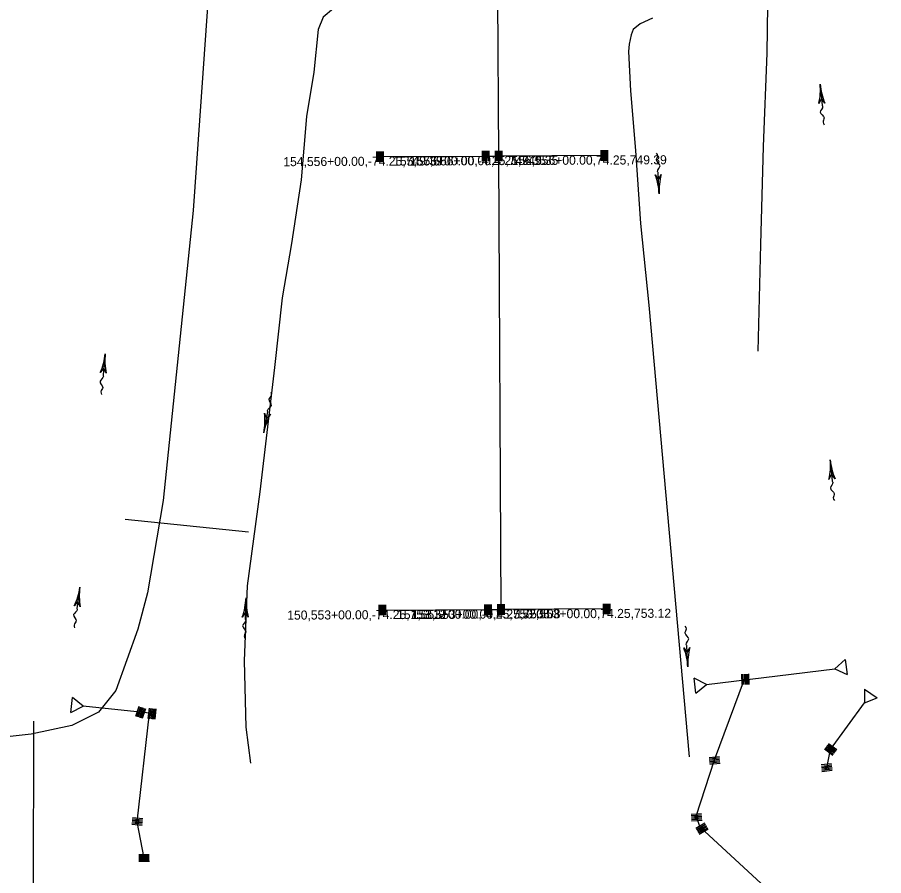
# Model space of a CAD drawing. Extents: x 593481 to 595859, y 150220 to 157407.
# Drawn here: x 594040 to 594613, y 154399 to 154967 of the extents above; entities that cross this region are included whole.
import ezdxf

# ---------------------------------------------------------------- set-up
doc = ezdxf.new("R2010")
doc.units = 0
for name, color, linetype in [('E_PROF_GridMin', 7, 'Continuous'), ('P_ALI_20_Tic', 7, 'Continuous'), ('P_ALI_50_Equation', 7, 'Continuous'), ('P_DRN_Pipes', 7, 'Continuous'), ('P_DRN_SS_UG', 7, 'Continuous'), ('P_RDWY_C_and_G_H', 7, 'Continuous')]:
    doc.layers.add(name, color=color, linetype=linetype)

msp = doc.modelspace()

# ---------------------------------------------------------------- linework, layer by layer
at = {"layer": 'E_PROF_GridMin'}
for p, q in [((594358.22, 154875.25), (594356.68, 155175.25)), ((594279.72, 154874.85), (594349.72, 154875.21)), ((594349.72, 154875.21), (594358.22, 154875.25)), ((594428.22, 154875.61), (594358.22, 154875.25)), ((594359.76, 154575.25), (594358.22, 154875.25)), ((594281.26, 154574.85), (594351.26, 154575.21)), ((594351.26, 154575.21), (594359.76, 154575.25)), ((594429.76, 154575.61), (594359.76, 154575.25)), ((594495.64, 154525.68), (594580.72, 154536.05)), ((594500.96, 154475.75), (594520.85, 154529.07)), ((594127.01, 154506.7), (594083.06, 154511.26)), ((594577.86, 154482.56), (594600.26, 154513.43)), ((594118.96, 154434.88), (594127.01, 154506.71)), ((594575.3, 154470.53), (594577.86, 154482.56)), ((594491.49, 154431.23), (594488.89, 154438.62)), ((594123.51, 154410.76), (594118.96, 154434.88)), ((594540.52, 154386.07), (594491.49, 154431.23))]:
    msp.add_line(p, q, dxfattribs=at)
for points in [[(594195.87, 155406.63), (594155.86, 154839.17), (594136.12, 154647.32), (594125.75, 154586.3), (594119.28, 154562.31), (594104.8, 154521.76), (594093.35, 154507.25), (594075.71, 154498.55), (594048.65, 154492.71), (593981.57, 154485.26), (593546.85, 154493.19), (593538.17, 154494.28), (593526.38, 154497.62), (593514.24, 154502.72), (593501.23, 154504.79), (593491.32, 154504.17), (593484.5, 154500.86), (593481.17, 154494.41)], [(594612.95, 155388.89), (594596.71, 155382.2), (594588.1, 155375.16), (594577.39, 155362.81), (594571.35, 155352.38), (594563.26, 155330.97), (594554.94, 155301.9), (594548.34, 155267.44), (594543.77, 155237.13), (594542.73, 155208.88), (594537.26, 155024.38), (594536.51, 155006.73), (594535.72, 154943.23), (594533.09, 154881.6), (594531.45, 154816.64), (594529.67, 154746.17)], [(594248.94, 154972.9), (594241.91, 154967.19), (594238.79, 154958.94), (594235.75, 154930.84), (594230.88, 154901.44), (594227.52, 154859.43), (594221.1, 154817.5), (594214.83, 154781.45), (594209.84, 154735.27), (594200.1, 154653.01), (594191.65, 154590.92), (594189.63, 154541.3), (594190.82, 154497.49), (594193.99, 154473.57)], [(594459.87, 154966.54), (594451.71, 154962.63), (594447.21, 154958.98), (594445.84, 154955.46), (594444.61, 154949.3), (594444.11, 154944.45), (594445.4, 154918.3), (594448.79, 154879.03), (594451.96, 154830.72), (594457.48, 154776.54), (594484.29, 154477.7)], [(594488.89, 154438.62), (594500.96, 154475.75)]]:
    msp.add_lwpolyline(points, dxfattribs=at)
at = {"layer": 'P_ALI_20_Tic'}
for p, q in [((594570.88, 154922.83), (594572.14, 154908.76)), ((594464.36, 154850.16), (594463.66, 154864.27)), ((594097.77, 154744.48), (594096.32, 154730.43)), ((594202.69, 154692.25), (594205.38, 154706.12)), ((594577.61, 154674.27), (594578.87, 154660.2)), ((594081.01, 154589.98), (594079.03, 154576)), ((594190.93, 154582.97), (594190.43, 154568.85)), ((594483.33, 154537.28), (594482.62, 154551.39))]:
    msp.add_line(p, q, dxfattribs=at)
for points in [[(594574.02, 154910.27), (594571.74, 154913.27), (594570.03, 154909.9)], [(594461.72, 154862.84), (594463.88, 154859.75), (594465.72, 154863.05)], [(594098.45, 154731.55), (594096.79, 154734.93), (594094.47, 154731.95)], [(594203.16, 154705.19), (594204.51, 154701.67), (594207.09, 154704.43)], [(594580.75, 154661.71), (594578.47, 154664.72), (594576.76, 154661.35)], [(594081.2, 154577.03), (594079.67, 154580.48), (594077.24, 154577.59)], [(594192.48, 154570.11), (594190.59, 154573.38), (594188.48, 154570.25)], [(594480.69, 154549.96), (594482.84, 154546.86), (594484.68, 154550.16)]]:
    msp.add_lwpolyline(points, dxfattribs=at)
for centre, start, end in [((594529.09, 154919.09), 347.35833, 5.12065), ((594612.67, 154926.58), 185.12065, 202.88297), ((594422.46, 154848.06), 2.86546, 20.62778), ((594506.27, 154852.26), 165.10314, 182.86546), ((594056.03, 154748.77), 336.36566, 354.12798), ((594139.51, 154740.19), 174.12798, 191.8903), ((594161.5, 154700.25), 349.00666, 6.76898), ((594243.87, 154684.25), 151.24434, 169.00666), ((594535.82, 154670.53), 347.35833, 5.12065), ((594619.4, 154678.02), 185.12065, 202.88297), ((594039.47, 154595.88), 334.15876, 351.92108), ((594122.55, 154584.09), 171.92108, 189.6834), ((594149, 154584.46), 340.19919, 357.96151), ((594232.86, 154581.48), 177.96151, 195.72383), ((594441.42, 154535.18), 2.86546, 20.62778), ((594525.23, 154539.37), 165.10314, 182.86546)]:
    msp.add_arc(centre, 41.96, start, end, dxfattribs=at)
for points in [[(594572.14, 154908.76), (594572.53, 154908.01), (594570.97, 154904.24), (594573.51, 154900.53), (594572.82, 154897.63), (594573.6, 154895.97)], [(594463.66, 154864.27), (594463.3, 154865.04), (594465, 154868.74), (594462.61, 154872.55), (594463.41, 154875.42), (594462.7, 154877.11)], [(594096.32, 154730.43), (594096.56, 154729.61), (594094.31, 154726.21), (594096.1, 154722.09), (594094.87, 154719.37), (594095.32, 154717.59)], [(594205.38, 154706.12), (594205.22, 154706.95), (594207.76, 154710.13), (594206.35, 154714.4), (594207.81, 154717), (594207.53, 154718.81)], [(594578.87, 154660.2), (594579.25, 154659.45), (594577.7, 154655.68), (594580.24, 154651.97), (594579.55, 154649.07), (594580.33, 154647.41)], [(594079.03, 154576), (594079.23, 154575.17), (594076.86, 154571.86), (594078.48, 154567.67), (594077.15, 154565), (594077.53, 154563.21)], [(594190.43, 154568.85), (594190.71, 154568.05), (594188.7, 154564.51), (594190.76, 154560.51), (594189.72, 154557.72), (594190.28, 154555.97)], [(594482.62, 154551.39), (594482.27, 154552.15), (594483.97, 154555.86), (594481.58, 154559.66), (594482.38, 154562.53), (594481.66, 154564.23)]]:
    msp.add_spline(points, degree=3, dxfattribs=at)
at = {"layer": 'P_DRN_Pipes'}
for p, q in [((594111.01, 154635.04), (594192.63, 154626.58)), ((594050.07, 154353.52), (594050.61, 154501.37))]:
    msp.add_line(p, q, dxfattribs=at)
at = {"layer": 'P_DRN_SS_UG'}
for p, q in [((594277.49, 154871.4), (594277.45, 154878.27)), ((594278.39, 154871.4), (594278.35, 154878.28)), ((594279.29, 154871.41), (594279.25, 154878.28)), ((594280.19, 154871.41), (594280.15, 154878.29)), ((594281.09, 154871.42), (594281.05, 154878.29)), ((594281.99, 154871.42), (594281.95, 154878.3)), ((594347.49, 154871.76), (594347.45, 154878.63)), ((594348.39, 154871.76), (594348.35, 154878.64)), ((594349.29, 154871.77), (594349.25, 154878.64)), ((594350.19, 154871.77), (594350.15, 154878.65)), ((594351.09, 154871.78), (594351.05, 154878.65)), ((594351.99, 154871.78), (594351.95, 154878.66)), ((594355.99, 154871.8), (594355.95, 154878.68)), ((594356.89, 154871.81), (594356.85, 154878.68)), ((594357.79, 154871.81), (594357.75, 154878.69)), ((594358.69, 154871.81), (594358.65, 154878.69)), ((594359.59, 154871.82), (594359.55, 154878.69)), ((594360.49, 154871.82), (594360.45, 154878.7)), ((594425.99, 154872.16), (594425.95, 154879.04)), ((594426.89, 154872.16), (594426.85, 154879.04)), ((594427.79, 154872.17), (594427.75, 154879.04)), ((594428.69, 154872.17), (594428.65, 154879.05)), ((594429.59, 154872.18), (594429.55, 154879.05)), ((594430.49, 154872.18), (594430.45, 154879.06)), ((594349.03, 154571.76), (594348.99, 154578.64)), ((594349.93, 154571.77), (594349.89, 154578.64)), ((594350.83, 154571.77), (594350.79, 154578.65)), ((594351.73, 154571.78), (594351.69, 154578.65)), ((594352.63, 154571.78), (594352.59, 154578.65)), ((594353.53, 154571.78), (594353.49, 154578.66)), ((594357.53, 154571.8), (594357.49, 154578.68)), ((594358.43, 154571.81), (594358.39, 154578.68)), ((594359.33, 154571.81), (594359.29, 154578.69)), ((594360.23, 154571.82), (594360.19, 154578.69)), ((594361.13, 154571.82), (594361.09, 154578.7)), ((594362.03, 154571.83), (594361.99, 154578.7)), ((594427.53, 154572.16), (594427.49, 154579.04)), ((594428.43, 154572.17), (594428.39, 154579.04)), ((594429.33, 154572.17), (594429.29, 154579.05)), ((594430.23, 154572.18), (594430.19, 154579.05)), ((594431.13, 154572.18), (594431.09, 154579.06)), ((594432.03, 154572.19), (594431.99, 154579.06)), ((594279.03, 154571.4), (594278.99, 154578.28)), ((594279.93, 154571.41), (594279.89, 154578.28)), ((594280.83, 154571.41), (594280.79, 154578.29)), ((594281.73, 154571.42), (594281.69, 154578.29)), ((594282.63, 154571.42), (594282.59, 154578.3)), ((594283.53, 154571.43), (594283.49, 154578.3)), ((594518.95, 154532.45), (594519.16, 154525.58)), ((594519.02, 154528.86), (594522.02, 154528.95)), ((594519.84, 154532.48), (594520.06, 154525.61)), ((594520.74, 154532.51), (594520.96, 154525.63)), ((594521.64, 154532.53), (594521.86, 154525.66)), ((594522.54, 154532.56), (594522.76, 154525.69)), ((594523.44, 154532.59), (594523.66, 154525.72)), ((594118.1, 154504.73), (594120.32, 154511.24)), ((594118.95, 154504.44), (594121.17, 154510.94)), ((594119.8, 154504.15), (594122.03, 154510.65)), ((594120.65, 154503.86), (594122.88, 154510.36)), ((594121.5, 154503.57), (594123.73, 154510.07)), ((594126.77, 154509.91), (594126.06, 154503.07)), ((594127.66, 154509.82), (594126.95, 154502.98)), ((594122.35, 154503.27), (594124.58, 154509.78)), ((594128.56, 154509.72), (594127.85, 154502.89)), ((594129.45, 154509.63), (594128.74, 154502.79)), ((594130.35, 154509.54), (594129.64, 154502.7)), ((594131.24, 154509.45), (594130.53, 154502.61)), ((594579.3, 154478.71), (594573.76, 154482.79)), ((594579.83, 154479.44), (594574.3, 154483.51)), ((594580.37, 154480.16), (594574.83, 154484.24)), ((594580.9, 154480.89), (594575.36, 154484.96)), ((594581.43, 154481.61), (594575.89, 154485.69)), ((594581.97, 154482.34), (594576.43, 154486.41)), ((594504.2, 154477.88), (594497.36, 154477.21)), ((594504.29, 154476.98), (594497.45, 154476.31)), ((594504.38, 154476.09), (594497.54, 154475.41)), ((594500.62, 154477.57), (594500.92, 154474.58)), ((594504.47, 154475.19), (594497.63, 154474.52)), ((594504.56, 154474.3), (594497.72, 154473.62)), ((594504.65, 154473.4), (594497.8, 154472.73)), ((594578.47, 154473.14), (594571.64, 154472.4)), ((594578.57, 154472.24), (594571.73, 154471.5)), ((594578.67, 154471.35), (594571.83, 154470.61)), ((594578.76, 154470.45), (594571.93, 154469.71)), ((594578.86, 154469.56), (594572.02, 154468.82)), ((594578.96, 154468.66), (594572.12, 154467.92)), ((594122.42, 154435.06), (594115.58, 154435.74)), ((594122.51, 154435.95), (594115.67, 154436.64)), ((594122.6, 154436.85), (594115.76, 154437.53)), ((594492.37, 154440.14), (594485.52, 154439.61)), ((594492.44, 154439.24), (594485.59, 154438.71)), ((594492.51, 154438.34), (594485.66, 154437.81)), ((594492.58, 154437.45), (594485.72, 154436.92)), ((594492.65, 154436.55), (594485.79, 154436.02)), ((594492.72, 154435.65), (594485.86, 154435.12)), ((594122.15, 154432.37), (594115.31, 154433.06)), ((594122.24, 154433.27), (594115.4, 154433.95)), ((594122.33, 154434.16), (594115.49, 154434.85)), ((594494.5, 154433.8), (594488.56, 154430.32)), ((594494.95, 154433.02), (594489.02, 154429.55)), ((594495.41, 154432.24), (594489.47, 154428.77)), ((594495.86, 154431.47), (594489.93, 154427.99)), ((594496.31, 154430.69), (594490.38, 154427.22)), ((594496.77, 154429.91), (594490.84, 154426.44)), ((594126.93, 154413.03), (594120.06, 154413)), ((594126.94, 154412.13), (594120.06, 154412.1)), ((594126.94, 154411.23), (594120.07, 154411.2)), ((594126.95, 154410.33), (594120.07, 154410.3)), ((594126.95, 154409.43), (594120.08, 154409.4)), ((594126.96, 154408.53), (594120.08, 154408.5))]:
    msp.add_line(p, q, dxfattribs=at)
for points in [[(594280.73, 154873.85), (594280.72, 154875.85), (594278.72, 154875.84), (594278.73, 154873.84)], [(594350.73, 154874.21), (594350.72, 154876.21), (594348.72, 154876.2), (594348.73, 154874.2)], [(594359.23, 154874.26), (594359.22, 154876.26), (594357.22, 154876.24), (594357.23, 154874.24)], [(594429.23, 154874.61), (594429.22, 154876.61), (594427.22, 154876.6), (594427.23, 154874.6)], [(594282.27, 154573.86), (594282.26, 154575.86), (594280.26, 154575.85), (594280.27, 154573.85)], [(594352.27, 154574.22), (594352.26, 154576.22), (594350.26, 154576.21), (594350.27, 154574.21)], [(594360.77, 154574.26), (594360.76, 154576.26), (594358.76, 154576.25), (594358.77, 154574.25)], [(594430.77, 154574.62), (594430.76, 154576.62), (594428.76, 154576.61), (594428.77, 154574.61)], [(594121.96, 154505.98), (594122.61, 154507.88), (594120.72, 154508.52), (594120.07, 154506.63)], [(594127.76, 154507.36), (594127.55, 154505.37), (594129.54, 154505.16), (594129.75, 154507.15)], [(594579.26, 154482.78), (594577.65, 154483.96), (594576.47, 154482.35), (594578.08, 154481.16)], [(594576.18, 154471.63), (594574.19, 154471.42), (594574.41, 154469.43), (594576.4, 154469.64)], [(594120.05, 154435.85), (594118.06, 154436.05), (594117.86, 154434.06), (594119.85, 154433.86)], [(594490.04, 154438.7), (594488.04, 154438.55), (594488.2, 154436.56), (594490.19, 154436.71)], [(594493.02, 154431.49), (594491.3, 154430.48), (594492.31, 154428.75), (594494.03, 154429.76)], [(594124.5, 154411.77), (594122.5, 154411.76), (594122.51, 154409.76), (594124.51, 154409.77)]]:
    msp.add_lwpolyline(points, close=True, dxfattribs=at)
at = {"layer": 'P_RDWY_C_and_G_H'}
for p, q in [((594587.38, 154542.13), (594580.72, 154536.05)), ((594587.38, 154542.13), (594588.89, 154532.25)), ((594580.72, 154536.05), (594588.89, 154532.25)), ((594495.64, 154525.68), (594487.64, 154529.84)), ((594488.73, 154519.9), (594487.64, 154529.84)), ((594488.73, 154519.9), (594495.64, 154525.68)), ((594600.31, 154522.45), (594600.26, 154513.43)), ((594600.31, 154522.45), (594608.6, 154516.86)), ((594075.06, 154507.18), (594076.16, 154517.12)), ((594083.06, 154511.32), (594076.16, 154517.12)), ((594600.26, 154513.43), (594608.6, 154516.86)), ((594075.06, 154507.18), (594083.06, 154511.32))]:
    msp.add_line(p, q, dxfattribs=at)

# ---------------------------------------------------------------- texts
at = {"layer": 'P_ALI_50_Equation'}
for s, p in [('154,556+00.00,-74.25,749.39', (594215.65, 154868.52)), ('155,556+00.00,-4.25,749.35', (594288.34, 154868.89)), ('157,556+00.00,4.25,749.35', (594299.3, 154868.95)), ('156,556+00.00,74.25,749.39', (594366.6, 154869.29)), ('150,553+00.00,-74.25,753.12', (594218.23, 154568.53)), ('151,553+00.00,-4.25,753.08', (594290.92, 154568.9)), ('153,553+00.00,4.25,753.08', (594300.65, 154568.95)), ('152,553+00.00,74.25,753.12', (594369.42, 154569.3))]:
    msp.add_text(s, height=6, rotation=0.29409, dxfattribs=at).set_placement(p)

doc.saveas('drawing.dxf')
